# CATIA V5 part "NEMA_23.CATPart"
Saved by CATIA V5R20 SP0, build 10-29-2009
Part number: NEMA_23
Bounding box of the stored display mesh (mm): x -31.534 to 24.866, y -36.51 to 21.89, z 14.8 to 95.3
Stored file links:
  C:\Users\Andi\Desktop\Plasma\NEMA_23.CATPart
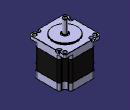
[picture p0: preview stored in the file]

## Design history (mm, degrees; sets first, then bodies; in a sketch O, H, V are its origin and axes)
Body1 (main body)
Body2 "NAUO10\\Répétition circulaire1"
  Solid1: solid without history
Body3 "NAUO8\\Enlèv. mat.-Extru.3"
  Solid2 "Volumen.1": solid without history
Body4 "NAUO5\\Enlèv. mat.-Extru.1"
  Solid3 "Volumen.1": solid without history
Body5 "NAUO3\\Congé1"
  Solid4 "Volumen.1": solid without history
Body6 "NAUO7\\Congé2"
  Solid5 "Volumen.1": solid without history
Body7 "NAUO2\\Répétition circulaire1"
  Solid6 "Volumen.1": solid without history
Body8 "NAUO6\\Enlèv. mat.-Extru.1"
  Solid7 "Volumen.1": solid without history
Body9 "NAUO4\\Enlèv. mat.-Extru.4"
  Solid8 "Volumen.1": solid without history
Body10 "NAUO9\\Répétition circulaire1"
  Solid9 "Volumen.1": solid without history
Body11 "NAUO1\\Répétition circulaire1"
  Solid10 "Volumen.1": solid without history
